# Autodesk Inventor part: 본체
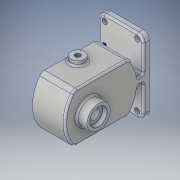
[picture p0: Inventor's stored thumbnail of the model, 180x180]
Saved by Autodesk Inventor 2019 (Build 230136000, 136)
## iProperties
Created: 2019-03
Part Number: 본체
Material: 알루미늄 6061
Document SubType Name: Modeling
Designer: User
Density: 2.7 g/cm^3
Appearance: 알루미늄 - 평지
Mass: 1187.1 g
Surface Area: 719.403 cm^2
Volume: 439.666 cm^3
Author: User
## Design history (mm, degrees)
sketch "스케치2"
  geometry: L1 (-51.1, 0)-(51.1, 0) reference; L2 (0, -84)-(0, 84) reference; L3 (36.5, 60)-(-36.5, 60); L4 (-36.5, 60)-(-36.5, -60); L5 (-36.5, -60)-(36.5, -60); L6 (36.5, -60)-(36.5, 60); 1 further point
  constraints: 8 end point, 2 parallel, 1 horizontal, 1 perpendicular, 2 other
  dimensions: "d4" = 73 distance of L3.start L3.end; "d5" = 120 distance of L3.end L4.end
extrude "돌출1" new body sketch "스케치2" stored distance "d2" = 10; taper "d3" = 0 deg
sketch "스케치3"
  geometry: L1 (0, 120)-(10, 120) reference; L2 (0, 0)-(0, 120) reference; L3 (10, 0)-(0, 0) reference; L4 (10, 120)-(10, 0) reference; L5 (5, -24)-(5, 144) reference; L6 (37.6, 60)-(-155.6, 60) reference; L7 (-68, 9.538)-(-68, 110.462); L8 (-112.721, 20)-(-68, 20); L9 (-68, 100)-(-112.721, 100); L10 (-23.279, 20)-(-68, 20); L11 (-68, 100)-(-23.279, 100); A1 r 60 centre (-68, 60) between (-112.721, 100) and (-112.721, 20); A2 r 60 centre (-68, 60) between (-23.279, 20) and (-23.279, 100); 1 further point
  constraints: 10 end point, 4 point on circle, 3 point on line, 3 symmetric about line, 2 centre point, 1 horizontal, 1 midpoint, 1 parallel, 1 vertical, 2 other
  dimensions: "d9" = 80 distance between parallel lines of L9 L8; "d10" = 78 distance between parallel lines of L4 L7; "d11" = 60 radius of A1
extrude "돌출2" join sketch "스케치3" distance "d12" = 53; taper "d13" = 0 deg
sketch "스케치4"
  geometry: L1 (-20, 54)-(10, 54); L2 (10, 54)-(10, 66); L3 (10, 66)-(-20, 66); L4 (-20, 66)-(-20, 54); L5 (10, 120)-(10, 0) reference; L6 (37.6, 60)-(-155.6, 60) reference; 1 further point
  constraints: 8 end point, 2 parallel, 1 collinear, 1 horizontal, 1 perpendicular, 1 other
  dimensions: "d14" = 12 distance of L1.end L2.end; "d15" = 30 distance of L1.start L1.end
extrude "돌출3" join sketch "스케치4" distance "d16" = 43; taper "d17" = 0 deg
sketch "스케치5"
  geometry: L1 (27.6, 60)-(-165.6, 60) reference; L2 (-5, -24)-(-5, 144) reference; L3 (0, 120)-(0, 0) reference; C1 r 19 at (-100, 60); 1 further point
  constraints: 1 centre point, 1 point on line
  dimensions: "d18" = 38 diameter of C1; "d19" = 100 distance from line of L3 C1.centre
extrude "돌출4" join sketch "스케치5" distance "d20" = 17; taper "d21" = 0 deg
sketch "스케치6"
  geometry: L1 (90, 60)-(46, 60); L2 (90, 84)-(46, 84); L3 (46, 36)-(90, 36); C1 r 19 at (90, 60) reference; A1 r 24 centre (90, 60) between (90, 36) and (90, 84); A2 r 24 centre (46, 60) between (46, 84) and (46, 36); 2 further points
  constraints: 8 end point, 4 point on circle, 4 tangent, 2 centre point, 1 concentric, 1 horizontal, 1 midpoint, 1 parallel
  dimensions: "d22" = 44 distance of L1.start L1.end; "d23" = 24 radius of A1
extrude "돌출5" cut sketch "스케치6" distance "d24" = 29; taper "d25" = 0 deg
sketch "스케치7"
  geometry: A1 r 24 centre (90, 60) between (90, 36) and (90, 84) reference; 2 further points
  constraints: 1 coincident
hole "구멍1" sketch "스케치7" at (90, 60) diameter "d26" = 17; stored, may be unused: countersink angle "d30" = 90 deg, drill point angle "d32" = 0 deg; dims "d27" = 18, "d28" = 25, "d29" = 15, "d31" = 22
sketch "스케치8"
  geometry: A1 r 24 centre (46, 60) between (46, 84) and (46, 36) reference; 2 further points
  constraints: 1 coincident
hole "구멍2" sketch "스케치8" at (46, 60) diameter "d33" = 25; stored, may be unused: countersink angle "d37" = 90 deg, drill point angle "d39" = 0 deg; dims "d34" = 18, "d35" = 25, "d36" = 15, "d38" = 15
sketch "스케치9"
  geometry: C1 r 19 at (0, 0) reference; 2 further points
  constraints: 1 coincident
hole "구멍3" sketch "스케치9" at (0, 0) diameter "d40" = 17; stored, may be unused: countersink angle "d44" = 90 deg, drill point angle "d46" = 0 deg; dims "d41" = 18, "d42" = 28, "d43" = 7.3, "d45" = 15
sketch "스케치10"
  geometry: L1 (-53, 66.721)-(-24, 66.721) reference; L2 (-91, -28.279)-(35, -28.279) reference; L3 (-36.5, -60.879)-(-36.5, 132.321) reference; L4 (-53, 0)-(-53, 89.443) reference; C1 r 11 at (-39, 44.721); 1 further point
  constraints: 1 centre point
  dimensions: "d47" = 22 distance from line of L1 C1.centre; "d48" = 22 diameter of C1; "d66" = 14 distance from line of L4 C1.centre
extrude "돌출6" join sketch "스케치10" distance "d49" = 8; taper "d50" = 0 deg
sketch "스케치11"
  geometry: C1 r 11 at (0, 0) reference; 2 further points
  constraints: 1 coincident
hole "구멍4" sketch "스케치11" at (0, 0) diameter "d51" = 8.376; stored, may be unused: countersink angle "d55" = 90 deg, drill point angle "d57" = 0 deg; dims "d52" = 27.3, "d53" = 28, "d54" = 7.3, "d56" = 27.3
fillet "모깎기1" dims "d58" = 10
sketch "스케치12"
  geometry: A1 r 10 centre (-26.5, 50) between (-26.5, 60) and (-36.5, 50) reference; A2 r 10 centre (26.5, -50) between (26.5, -60) and (36.5, -50) reference; A3 r 10 centre (-26.5, -50) between (-36.5, -50) and (-26.5, -60) reference; 5 further points
  constraints: 3 coincident
hole "구멍5" sketch "스케치12" at (-26.5, 50), (26.704, 51.813), (26.5, -50), (-26.5, -50) diameter "d59" = 9; stored, may be unused: countersink angle "d63" = 90 deg, drill point angle "d65" = 0 deg; dims "d60" = 20, "d61" = 28, "d62" = 7.3, "d64" = 27.3
sketch "스케치13"
  geometry: L1 (90, 60)-(46, 60); L2 (90, 91)-(46, 91); L3 (46, 29)-(90, 29); L4 (121, 60)-(15, 60); L5 (90, 91)-(90, 29); L6 (90, 36)-(46, 36) reference; L7 (46, 91)-(46, 29); C1 r 8.5 at (90, 60) reference; A1 r 31 centre (90, 60) between (90, 29) and (90, 91); A2 r 31 centre (46, 60) between (46, 91) and (46, 29); 8 further points
  constraints: 14 end point, 6 coincident, 6 point on circle, 4 tangent, 2 centre point, 1 horizontal, 1 midpoint, 1 parallel, 1 perpendicular, 1 vertical
  dimensions: "d67" = 44 distance of L1.start L1.end; "d68" = 31 radius of A1
hole "구멍6" sketch "스케치13" at (121, 60), (90, 91), (46, 91), (15, 60), (46, 29), (90, 29) diameter "d69" = 4.134; stored, may be unused: countersink angle "d73" = 90 deg, drill point angle "d75" = 118 deg; dims "d70" = 10, "d71" = 28, "d72" = 7.3, "d74" = 12
chamfer "모따기1" distance "d76" = 0.7; stored, may be unused: second distance "d77" = 2, angle "d78" = 30 deg
fillet "모깎기2" dims "d79" = 0.5
chamfer "모따기2" distance "d80" = 1; stored, may be unused: second distance "d81" = 2, angle "d82" = 45 deg
fillet "모깎기3" dims "d83" = 10
fillet "모깎기4" dims "d84" = 3
fillet "모깎기5" dims "d85" = 3
fillet "모깎기6" dims "d86" = 3
fillet "모깎기7" dims "d87" = 3
fillet "모깎기8" dims "d88" = 3
fillet "모깎기9" dims "d89" = 3
sketch "스케치14"
  geometry: L1 (-54.5, 0)-(71.5, 0) reference; L2 (-36.5, 50)-(-36.5, -50) reference; L3 (26.5, 60)-(-26.5, 60) reference; 2 further points
  constraints: 1 other
  dimensions: "d90" = 10 distance from line of point (-26.5, 0) L2; "d91" = 60 distance from line of L3 point (-26.5, 0)
feature "엠보싱1" sketch "스케치14" dims "d92" = 0.5, "d93" = 0
node "솔리드1"
mirror "미러1"
mirror "미러2"
node "투영된 루프1"
